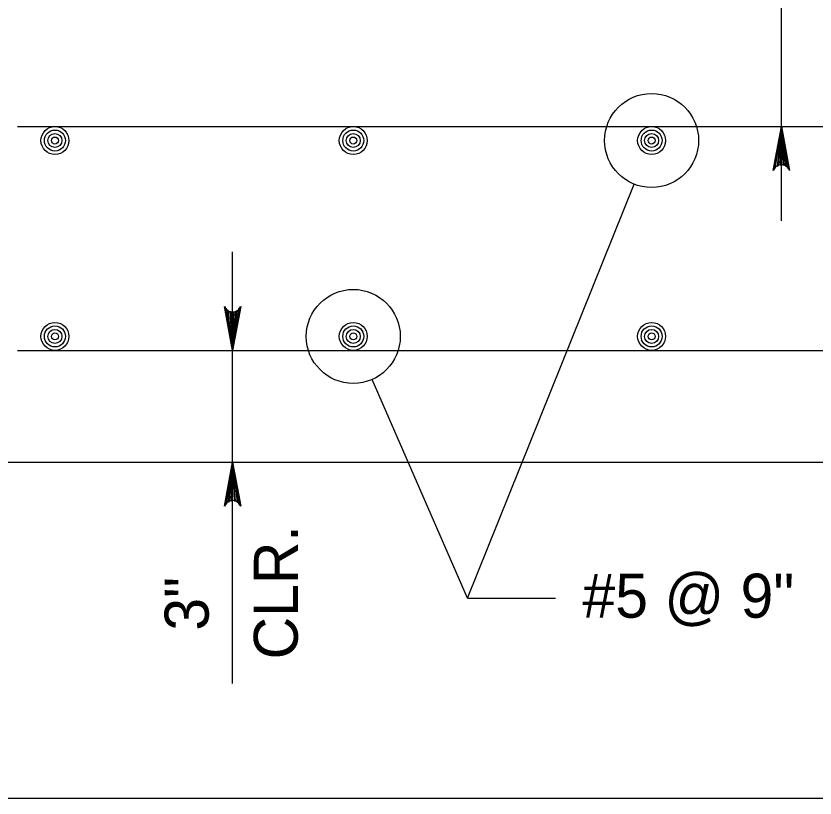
# Model space of a CAD drawing. Extents: x 638079 to 640019, y 297691 to 298879.
# Drawn here: x 639273.2 to 639327.7, y 298483.1 to 298536.4 of the extents above; entities that cross this region are included whole.
import ezdxf

# ---------------------------------------------------------------- set-up
doc = ezdxf.new("R2010")
doc.units = 0
doc.layers.add('1', color=7, linetype='Continuous')

msp = doc.modelspace()

# ---------------------------------------------------------------- linework, layer by layer
at = {"layer": '1'}
for p, q in [((639325.382, 298522.444), (639325.382, 298556.839)), ((639273.36, 298528.862), (639441, 298528.862)), ((639316.54, 298527.911), (639316.54, 298527.911)), ((639304.01, 298496.746), (639315.346, 298524.942)), ((639288.001, 298490.929), (639288.001, 298520.341)), ((639296.22, 298514.573), (639296.22, 298514.573)), ((639273.36, 298513.622), (639441, 298513.622)), ((639304.01, 298496.746), (639297.501, 298511.641)), ((639265.74, 298506.002), (639448.62, 298506.002)), ((639304.01, 298496.746), (639309.996, 298496.746)), ((639250.5, 298483.142), (639463.86, 298483.142))]:
    msp.add_line(p, q, dxfattribs=at)
for points in [[(639325.382, 298528.862), (639325.941, 298525.88), (639325.862, 298525.995), (639325.782, 298526.11), (639325.682, 298526.169), (639325.582, 298526.228), (639325.482, 298526.245), (639325.382, 298526.262), (639325.282, 298526.245), (639325.182, 298526.228), (639325.082, 298526.169), (639324.982, 298526.11), (639324.903, 298525.995), (639324.823, 298525.88), (639325.382, 298528.862), (639324.903, 298525.995), (639324.982, 298526.11), (639325.382, 298528.862), (639325.082, 298526.169), (639325.182, 298526.228), (639325.382, 298528.862), (639325.282, 298526.245), (639325.382, 298526.262), (639325.382, 298528.862), (639325.482, 298526.245), (639325.582, 298526.228), (639325.382, 298528.862), (639325.682, 298526.169), (639325.782, 298526.11), (639325.382, 298528.862), (639325.862, 298525.995)], [(639288.001, 298513.622), (639287.442, 298516.605), (639287.522, 298516.49), (639287.601, 298516.375), (639287.701, 298516.316), (639287.801, 298516.257), (639287.901, 298516.239), (639288.001, 298516.222), (639288.101, 298516.239), (639288.201, 298516.257), (639288.301, 298516.316), (639288.401, 298516.375), (639288.481, 298516.49), (639288.561, 298516.605), (639288.001, 298513.622), (639288.481, 298516.49), (639288.401, 298516.375), (639288.001, 298513.622), (639288.301, 298516.316), (639288.201, 298516.257), (639288.001, 298513.622), (639288.101, 298516.239), (639288.001, 298516.222), (639288.001, 298513.622), (639287.901, 298516.239), (639287.801, 298516.257), (639288.001, 298513.622), (639287.701, 298516.316), (639287.601, 298516.375), (639288.001, 298513.622), (639287.522, 298516.49)], [(639273.602, 298505.998), (639273.612, 298506.002)], [(639288.001, 298506.002), (639288.561, 298503.02), (639288.481, 298503.135), (639288.401, 298503.25), (639288.301, 298503.309), (639288.201, 298503.368), (639288.101, 298503.385), (639288.001, 298503.402), (639287.901, 298503.385), (639287.801, 298503.368), (639287.701, 298503.309), (639287.601, 298503.25), (639287.522, 298503.135), (639287.442, 298503.02), (639288.001, 298506.002), (639287.522, 298503.135), (639287.601, 298503.25), (639288.001, 298506.002), (639287.701, 298503.309), (639287.801, 298503.368), (639288.001, 298506.002), (639287.901, 298503.385), (639288.001, 298503.402), (639288.001, 298506.002), (639288.101, 298503.385), (639288.201, 298503.368), (639288.001, 298506.002), (639288.301, 298503.309), (639288.401, 298503.25), (639288.001, 298506.002), (639288.481, 298503.135)]]:
    msp.add_lwpolyline(points, dxfattribs=at)
for centre, radius in [((639316.54, 298527.911), 3.2), ((639275.899, 298527.911), 0.952), ((639296.22, 298527.911), 0.952), ((639316.54, 298527.911), 0.952), ((639275.899, 298527.911), 0.714), ((639275.899, 298527.911), 0.476), ((639296.22, 298527.911), 0.714), ((639296.22, 298527.911), 0.476), ((639316.54, 298527.911), 0.714), ((639316.54, 298527.911), 0.476), ((639275.899, 298527.911), 0.238), ((639296.22, 298527.911), 0.238), ((639316.54, 298527.911), 0.238), ((639296.22, 298514.573), 3.2), ((639275.899, 298514.573), 0.952), ((639275.899, 298514.573), 0.714), ((639296.22, 298514.573), 0.952), ((639296.22, 298514.573), 0.714), ((639316.54, 298514.573), 0.952), ((639316.54, 298514.573), 0.714), ((639275.899, 298514.573), 0.476), ((639275.899, 298514.573), 0.238), ((639296.22, 298514.573), 0.476), ((639296.22, 298514.573), 0.238), ((639316.54, 298514.573), 0.476), ((639316.54, 298514.573), 0.238)]:
    msp.add_circle(centre, radius, dxfattribs=at)

# ---------------------------------------------------------------- texts
for s, p in [('CLR.', (639292.444, 298492.578)), ('3"', (639286.372, 298494.539))]:
    msp.add_text(s, height=3, rotation=90, dxfattribs=at).set_placement(p)
msp.add_text('#5 @ 9"', height=3, dxfattribs=at).set_placement((639311.834, 298495.418))

doc.saveas('drawing.dxf')
